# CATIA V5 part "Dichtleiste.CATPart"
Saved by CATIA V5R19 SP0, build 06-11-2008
Bounding box of the stored display mesh (mm): x 0 to 30, y -1 to 1, z -10.5 to 4.5
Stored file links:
  H:\Bachelorarbeit_Hahn\Neue Vereinfachung\Dichtleiste.CATPart
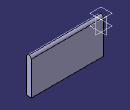
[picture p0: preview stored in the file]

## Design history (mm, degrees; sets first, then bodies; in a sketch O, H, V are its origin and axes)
Body1 (main body)
  Sketch1 on yz-plane, origin (0, 0, 0), H (0, 1, 0), V (0, 0, 1)
    line L1 (1, 3.5) -> (1, -10.5)
    line L2 (1, -10.5) -> (-1, -10.5)
    line L3 (-1, -10.5) -> (-1, 3.5)
    point P5 (0, 4.5)
    arc A1 centre (0, 3.5) radius 1 from (1, 3.5) to (0, 4.5) ccw
    point P6 (0, 3.5)
    arc A2 centre (0, 3.5) radius 1 from (0, 4.5) to (-1, 3.5) ccw
    distance L1 L3 = 2
    distance P5 L2 = 15
    vertical: L1 V, L3 V
    horizontal: L2 H
    equidistance: L1 L3 O
    coincidence: P5 V, P6 V
    tangency: A1 L1, A2 L1
  Pad1: profile Sketch1, direction (1, 0, 0), length 30
  Plane1: type Offset, Offset 4.5, RefPlane xy-plane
